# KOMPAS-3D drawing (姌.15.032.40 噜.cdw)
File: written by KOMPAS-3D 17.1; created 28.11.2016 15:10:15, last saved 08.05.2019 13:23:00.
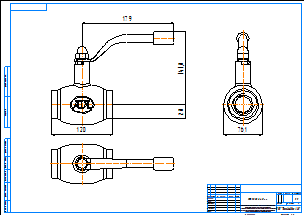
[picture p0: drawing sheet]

Sheet 1: A2, landscape

Title block, sheet 1: name: КШ.15.032.40 рр; material: Внимание! Данный продукт является объектом авторского права ООО «Торговый Дом АДЛ». / Запрещается изменение, копирование, распространение / (в том числе путем копирования на другие сайты и ресурсы в Интернете) / или любое иное использование информации и объектов без предварительного / согласия правообладателя (ООО «Торговый Дом АДЛ»).; sheets: 1; organisation: ООО "Торговый дом АДЛ"; sheet format: A2; stored path: C:\Users\tra\Desktop\2д чертежи\Шаровые краны БИВАЛ\КШ_Бивал_серия_14_15\KOMPAS_2D\КШ.15.032.40 рр.cdw

Views: Вид 1, Проекционный вид 2, Проекционный вид 3
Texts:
  Klimkovich
  ADL
Dimensions and other numbers on the sheet: 120; 179; 141,8; 28; 76,1; 1:1; 1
